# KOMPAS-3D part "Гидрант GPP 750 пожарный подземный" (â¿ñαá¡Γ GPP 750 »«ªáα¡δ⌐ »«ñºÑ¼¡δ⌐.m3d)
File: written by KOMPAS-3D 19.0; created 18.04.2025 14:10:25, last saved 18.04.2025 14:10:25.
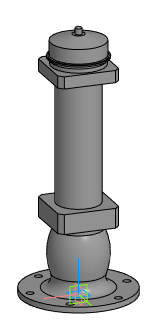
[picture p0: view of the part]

Document properties: Полное имя файла: E:\Dendor Работа Сачек\3D для проекитирвщиков\11.1 Тип GPP. Гидрант пожарный подземный\stp_Тип GPP. 750-6000 Гидрант пожарный подземный\Гидрант GPP 750 пожарный подземный.m3d

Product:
- Part/product: Гидрант GPP 750 пожарный подземный

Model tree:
1. Операция без истории:1  (labels: Гидрант GPP 750 пожарный подземный)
